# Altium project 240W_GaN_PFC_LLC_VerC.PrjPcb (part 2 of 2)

## Sheet 240W_LLC_Stage.SchDoc
size 431 x 279 mm; Date: Not shown in title block; ApprovedBy: Not shown in title block; CheckedBy: Not shown in title block; Author: Not shown in title block; CompanyName: Not shown in title block; Engineer: Not shown in title block; Organization: Not shown in title block; Address1: Not shown in title block; Address2: Not shown in title block; Address3: Not shown in title block; Address4: Not shown in title block; DocumentNumber: 3; Revision: Use project parameter SCH_Rev; SheetNumber: 3; SheetTotal: 3; PageSetup: Record=PageOptions¦CenterHorizontal=True¦CenterVertical=True¦PrintScale=1.00¦XCorrection=1.00¦YCorrection=1.00¦PrintKind=0¦BorderSize=5000000¦LeftOffset=0¦BottomOffset=0¦Orientation=2¦PaperLength=1000¦PaperWidth=1000¦Scale=100¦PaperSource=15¦PrintQuality=600¦MediaType=1¦DitherType=10¦PaperKind=Letter¦PrintScaleMode=1
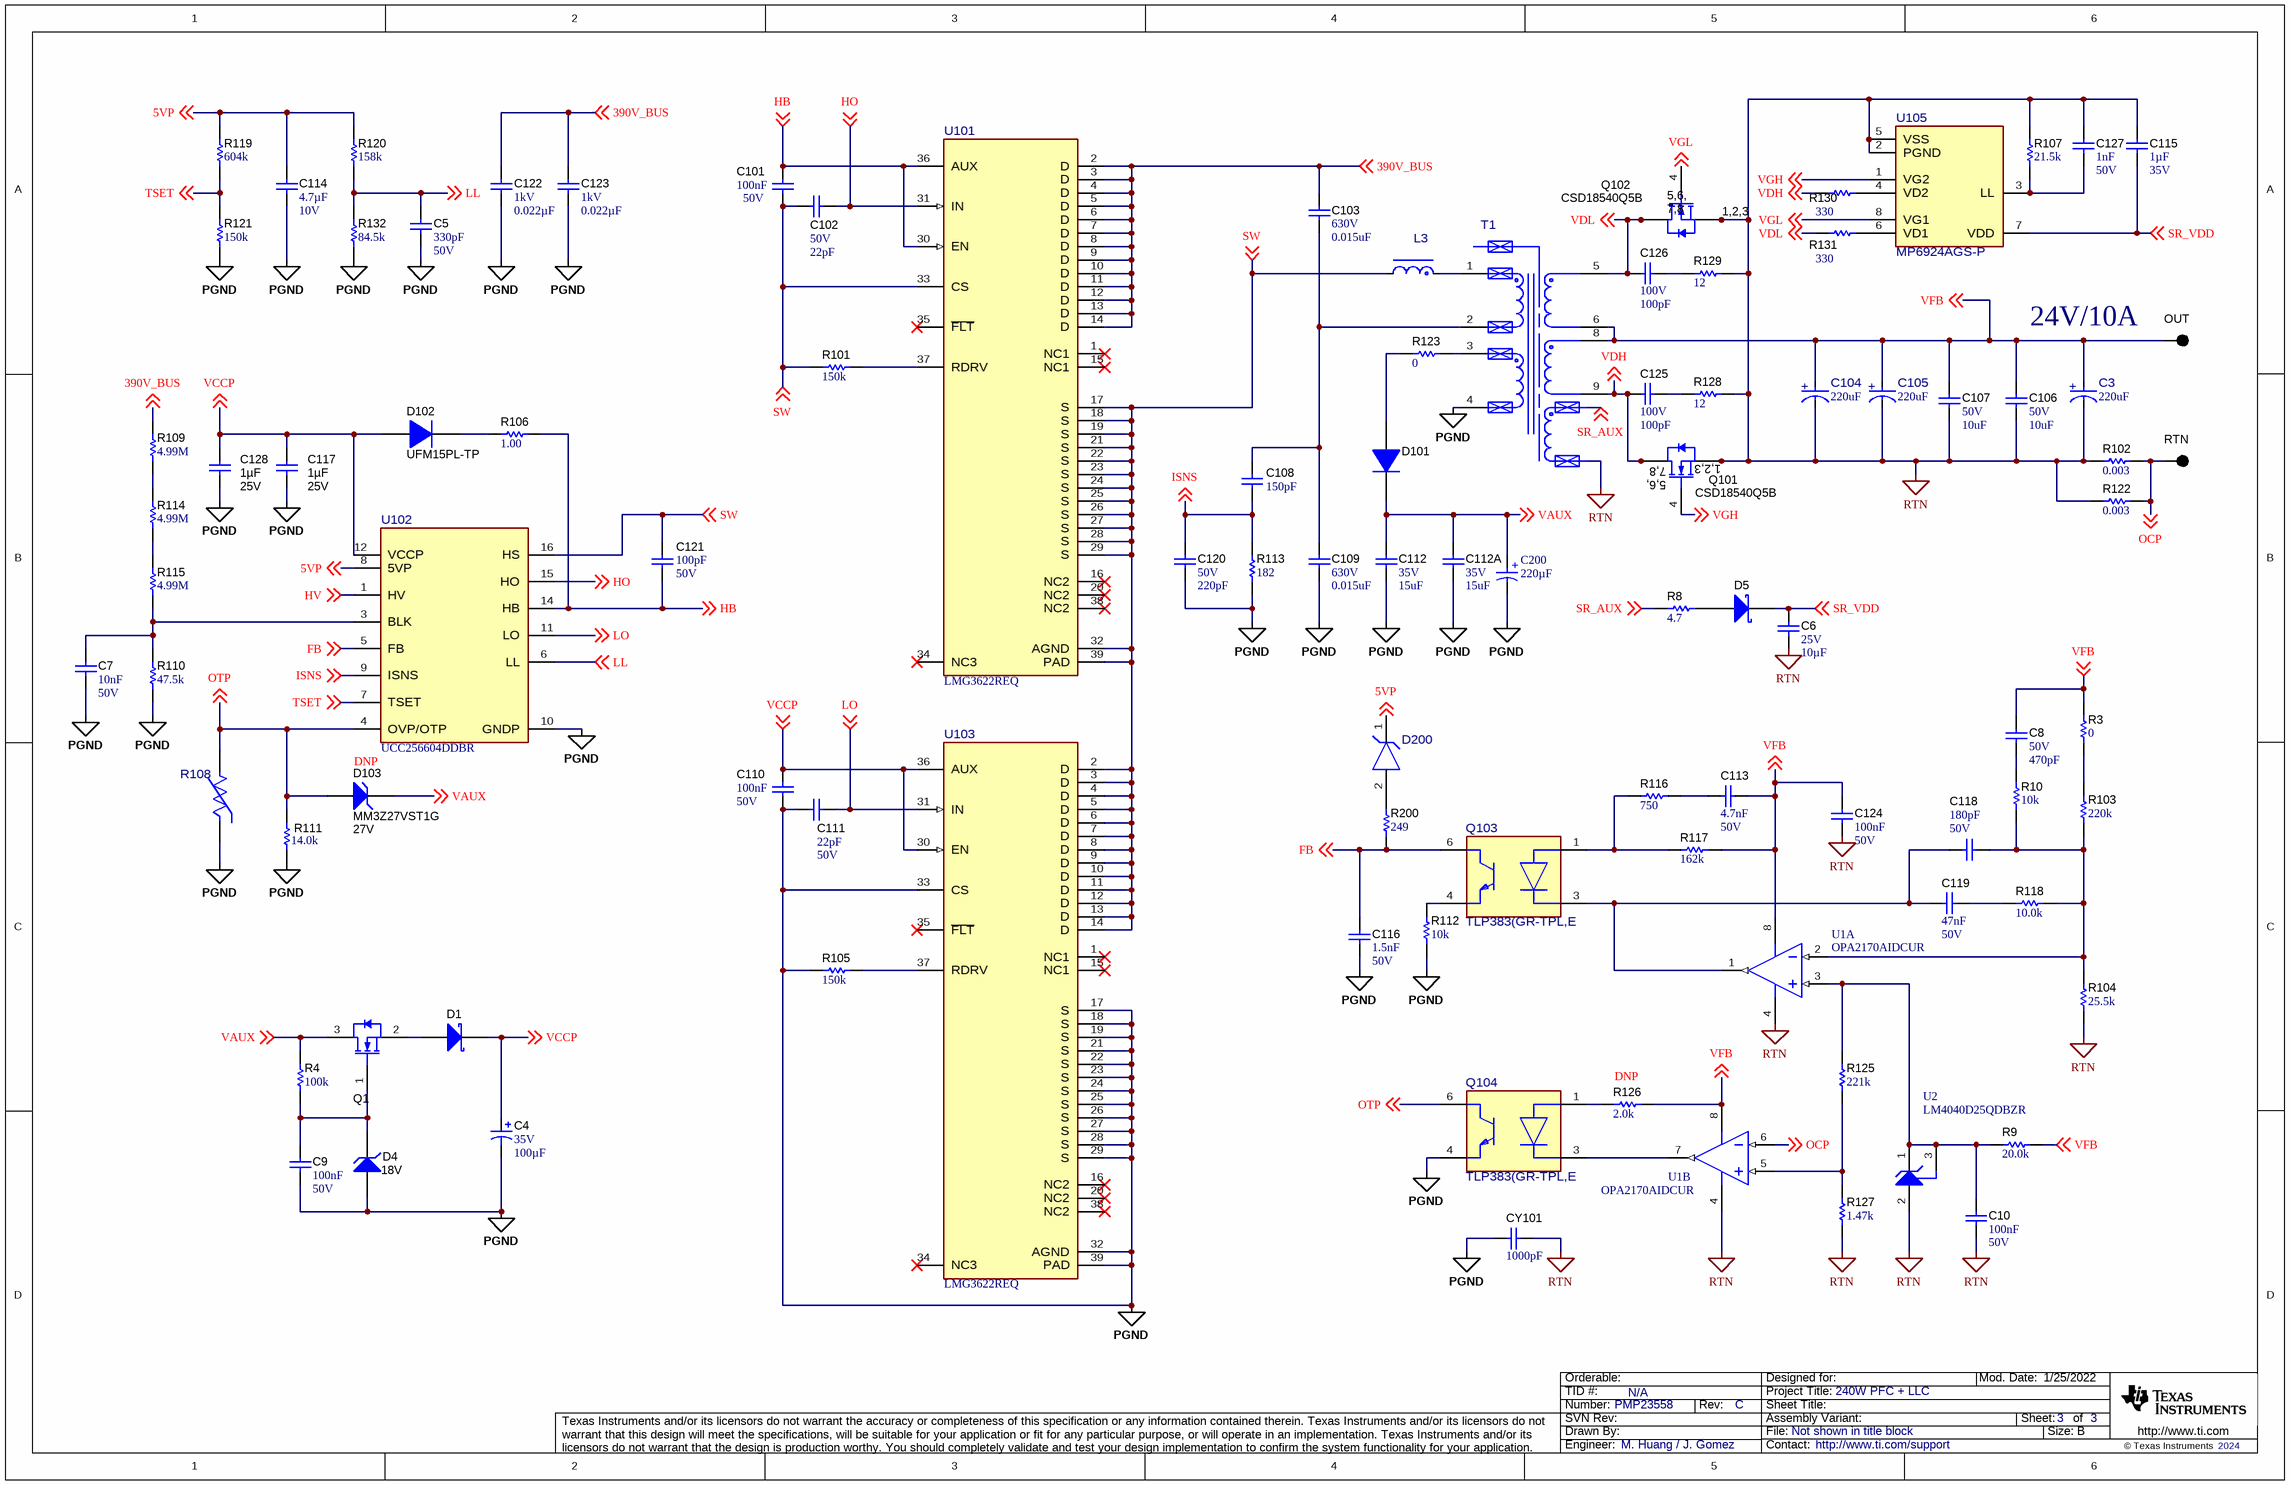
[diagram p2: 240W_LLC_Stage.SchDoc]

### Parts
C3  ValueDisplayed: 220uF  [FP-227AVG035MFBJ_RADIAL-MFG]  (hidden comment: 227AVG035MFBJ)
C4  VDC_V: 35V  ValueDisplayed: 100µF  [Rubycon_630x1100]  (hidden comment: 35ZLJ100M6.3X11)
C5  Cap_F: 330pF  VDC_V: 50V  [0603_HV]  (hidden comment: C0603C331K5RACTU)
C6  VDC_V: 25V  ValueDisplayed: 10µF  [0603_HV]  (hidden comment: GRM188R61E106KA73D)
C7  Cap_F: 10nF  VDC_V: 50V  [0603_HV]  (hidden comment: C0603C103K5RACTU)
C8  VDC_V: 50V  ValueDisplayed: 470pF  [0603_HV]  (hidden comment: 06035A471JAT2A)
C9  Cap_F: 100nF  VDC_V: 50V  [0603_HV]  (hidden comment: GCM188R71H104KA57D)
C10  Cap_F: 100nF  VDC_V: 50V  [0603_HV]  (hidden comment: 06035C104KAZ2A)
C101  Cap_F: 100nF  VDC_V: 50V  [0603_HV]  (hidden comment: 06035C104KAZ2A)
C102  VDC_V: 50V  ValueDisplayed: 22pF  [0603_HV]  (hidden comment: CGA3E2C0G1H220J080AA)
C103  VDC_V: 630V  ValueDisplayed: 0.015uF  [PHE426_1300x400x900]  (hidden comment: PHE426MA5150JR05)
C104  ValueDisplayed: 220uF  [FP-227AVG035MFBJ_RADIAL-MFG]  (hidden comment: 227AVG035MFBJ)
C105  ValueDisplayed: 220uF  [FP-227AVG035MFBJ_RADIAL-MFG]  (hidden comment: 227AVG035MFBJ)
C106  VDC_V: 50V  ValueDisplayed: 10uF  [1206_180M]  (hidden comment: CL31B106KBHNNNE)
C107  VDC_V: 50V  ValueDisplayed: 10uF  [1206_180M]  (hidden comment: CL31B106KBHNNNE)
C108  ValueDisplayed: 150pF  [1206]  (hidden comment: GRM31A5C2J151JW01D)
C109  VDC_V: 630V  ValueDisplayed: 0.015uF  [PHE426_1300x400x900]  (hidden comment: PHE426MA5150JR05)
C110  Cap_F: 100nF  VDC_V: 50V  [0603_HV]  (hidden comment: 06035C104KAZ2A)
C111  VDC_V: 50V  ValueDisplayed: 22pF  [0603_HV]  (hidden comment: CGA3E2C0G1H220J080AA)
C112  VDC_V: 35V  ValueDisplayed: 15uF  [0805_HV]  (hidden comment: C2012X5R1V156M125AC)
C112A  VDC_V: 35V  ValueDisplayed: 15uF  [0805_HV]  (hidden comment: C2012X5R1V156M125AC)
C113  Cap_F: 4.7nF  VDC_V: 50V  [0603_HV]  (hidden comment: C0603C472K5RACTU)
C114  Cap_F: 4.7µF  VDC_V: 10V  [0603_HV]  (hidden comment: GRM188Z71A475ME15D)
C115  Cap_F: 1µF  VDC_V: 35V  [0603_HV]  (hidden comment: C1608X7R1V105K080AC)
C116  Cap_F: 1.5nF  VDC_V: 50V  [0603_HV]  (hidden comment: GRM188R71H152KA01D)
C117  Cap_F: 1µF  VDC_V: 25V  [0603_HV]  (hidden comment: GRJ188R71E105KE11D)
C118  VDC_V: 50V  ValueDisplayed: 180pF  [0603_HV]  (hidden comment: 06035A181JAT2A)
C119  Cap_F: 47nF  VDC_V: 50V  [0603_HV]  (hidden comment: C1608X7R1H473K080AA)
C120  VDC_V: 50V  ValueDisplayed: 220pF  [0603_HV]  (hidden comment: GRM1885C1H221JA01D)
C121  VDC_V: 50V  ValueDisplayed: 100pF  [0603]  (hidden comment: C0603C101F5GACTU)
C122  VDC_V: 1kV  ValueDisplayed: 0.022µF  [1206_190]  (hidden comment: C1206C223KDRACTU)
C123  VDC_V: 1kV  ValueDisplayed: 0.022µF  [1206_190]  (hidden comment: C1206C223KDRACTU)
C124  Cap_F: 100nF  VDC_V: 50V  [0603_HV]  (hidden comment: C0603C104K5RACTU)
C125  VDC_V: 100V  ValueDisplayed: 100pF  [0603]  (hidden comment: C1608C0G2A101F080AA)
C126  VDC_V: 100V  ValueDisplayed: 100pF  [0603]  (hidden comment: C1608C0G2A101F080AA)
C127  Cap_F: 1nF  VDC_V: 50V  [0603_HV]  (hidden comment: C0603X102K5RACTU)
C128  Cap_F: 1µF  VDC_V: 25V  [0603_HV]  (hidden comment: GRJ188R71E105KE11D)
C200  Cap_F: 220µF  [WCAP-ATUL_D10H12.5]  (hidden comment: 860040575007)
CY101  ValueDisplayed: 1000pF  [DK1_86]  (hidden comment: DK1E3EA102M86RAH01)
D1  SD103AWS-TP  [SOD-323]  (value not drawn)
D4  value 18V  [SOD-323]  (hidden comment: MMSZ5248BS-7-F)
D5  SD103AWS-TP  [SOD-323]  (value not drawn)
D101  ES1D-E3/61T  [SMA]  (value not drawn)
D102  UFM15PL-TP  [SOD-123FL]
D103  MM3Z27VST1G  value 27V  [SOD-323]
D200  BZX84J-C3V0,115  [FP-BZX84J-B4V7,115_SC90-MFG]  (value not drawn)
L3  (no value)  [FP-G244038LF_PTH2-MFG]
Q1  2N7002-7-F  [SOT-23]  (value not drawn)
Q101  CSD18540Q5B  [DNK0008A]
Q102  CSD18540Q5B  [DNK0008A]
Q103  TLP383(GR-TPL,E  [FP-TLP383(GR-TPL,E_SO6-4-MFG]
Q104  TLP383(GR-TPL,E  [FP-TLP383(GR-TPL,E_SO6-4-MFG]
R3  ValueDisplayed: 0  [0603_HV]  (hidden comment: RC0603JR-070RL)
R4  ValueDisplayed: 100k  [0603_HV]  (hidden comment: CRCW0603100KJNEAC)
R8  ValueDisplayed: 4.7  [0603_HV]  (hidden comment: CRCW06034R70JNEA)
R9  ValueDisplayed: 20.0k  [0603_HV]  (hidden comment: CRCW060320K0FKEA)
R10  ValueDisplayed: 10k  [0603_HV]  (hidden comment: CRCW060310K0JNEA)
R101  ValueDisplayed: 150k  [0603]  (hidden comment: CRCW0603150KJNEA)
R102  ValueDisplayed: 0.003  [1206]  (hidden comment: CSNL1206FT3L00)
R103  ValueDisplayed: 220k  [0603_HV]  (hidden comment: RC0603FR-07220KL)
R104  ValueDisplayed: 25.5k  [0603_HV]  (hidden comment: RC0603FR-0725K5L)
R105  ValueDisplayed: 150k  [0603_HV]  (hidden comment: CRCW0603150KJNEA)
R106  ValueDisplayed: 1.00  [0603_HV]  (hidden comment: RC0603FR-071RL)
R107  ValueDisplayed: 21.5k  [0603_HV]  (hidden comment: RC0603FR-0721K5L)
R108  B57371V2474J060  [FP-B57371V2474J060_0603-MFG]  (value not drawn)
R109  ValueDisplayed: 4.99M  [0805_HV]  (hidden comment: CRCW08054M99FKEA)
R110  ValueDisplayed: 47.5k  [0603]  (hidden comment: RC0603FR-0747K5L)
R111  ValueDisplayed: 14.0k  [0603_HV]  (hidden comment: RC0603FR-0714KL)
R112  ValueDisplayed: 10k  [0603_HV]  (hidden comment: RC0603JR-0710KL)
R113  ValueDisplayed: 182  [0603]  (hidden comment: RC0603FR-07182RL)
R114  ValueDisplayed: 4.99M  [0805_HV]  (hidden comment: CRCW08054M99FKEA)
R115  ValueDisplayed: 4.99M  [0805_HV]  (hidden comment: CRCW08054M99FKEA)
R116  ValueDisplayed: 750  [0603_HV]  (hidden comment: CRCW0603750RFKEA)
R117  ValueDisplayed: 162k  [0603]  (hidden comment: RC0603FR-07162KL)
R118  ValueDisplayed: 10.0k  [0603_HV]  (hidden comment: M55342K12B10E0T)
R119  ValueDisplayed: 604k  [0603]  (hidden comment: CRCW0603604KFKEA)
R120  ValueDisplayed: 158k  [0603]  (hidden comment: RC0603FR-07158KL)
R121  ValueDisplayed: 150k  [0603]  (hidden comment: RC0603FR-07150KL)
R122  ValueDisplayed: 0.003  [1206]  (hidden comment: CSNL1206FT3L00)
R123  ValueDisplayed: 0  [0603]  (hidden comment: CRCW06030000Z0EA)
R125  ValueDisplayed: 221k  [0603]  (hidden comment: RC0603FR-07221KL)
R126  ValueDisplayed: 2.0k  [0603_HV]  (hidden comment: CRCW06032K00JNEA)
R127  ValueDisplayed: 1.47k  [0603_HV]  (hidden comment: RC0603FR-071K47L)
R128  ValueDisplayed: 12  [0805_HV]  (hidden comment: ERJ-6GEYJ120V)
R129  ValueDisplayed: 12  [0805_HV]  (hidden comment: ERJ-6GEYJ120V)
R130  ValueDisplayed: 330  [0603_HV]  (hidden comment: RC0603JR-07330RL)
R131  ValueDisplayed: 330  [0603_HV]  (hidden comment: RC0603JR-07330RL)
R132  ValueDisplayed: 84.5k  [0603]  (hidden comment: RC0603FR-0784K5L)
R200  ValueDisplayed: 249  [0603]  (hidden comment: CRCW0603249RFKEA)
T1  (no value)  [FP-G244036LF_PTH_XFRMR_29MM0_20MM6-MFG]
TP101  OUT  [Keystone5011]
TP106  RTN  [Keystone5011]
U1  OPA2170AIDCUR  [DCU0008A_N]  (parts A,B of 2)
U2  LM4040D25QDBZR  [DBZ0003A_N]
U101  LMG3622REQ  [REQ0038A-MFG]
U102  UCC256604DDBR  [DDB0014A-MFG]
U103  LMG3622REQ  [REQ0038A-MFG]
U105  MP6924AGS-P  [FP-MP6924AGS-P_SOIC8-MFG]

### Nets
PGND: C4.2(-) C5.2 C7.2 C9.2 C109.2 C110.2 C111.2 C112.2 C112A.2 C114.2 C116.2 C117.1 C120.2 C122.2 C123.2 C128.1 C200.2(N) CY101.2 D4.2(A) Q104.4(Emitter) R105.1 R108.1 R110.1 R111.1 R112.1 R113.1 R121.1 R132.1 T1.4 U102.10(GNDP) U103.17(S) U103.18(S) U103.19(S) U103.21(S) U103.22(S) U103.23(S) U103.24(S) U103.25(S) U103.26(S) U103.27(S) U103.28(S) U103.29(S) U103.32(AGND) U103.33(CS) U103.39(PAD)
RTN: C3.1(CATHODE) C6.2 C10.2 C104.1(CATHODE) C105.1(CATHODE) C106.2 C107.2 C115.2 C124.2 C127.1 CY101.1 Q101.1(S) Q101.2(S) Q101.3(S) Q102.1(S) Q102.2(S) Q102.3(S) R102.1 R104.1 R107.1 R122.1 R127.1 R128.2 R129.2 U1.4(V-) U2.2(ANODE) U105.2(PGND) U105.5(VSS)
5VP: C114.1 D200.1(cathode) R119.2 R120.2 U102.8(5VP) ; off-sheet 5VP
390V_BUS: C103.1 C122.1 C123.1 R109.2 U101.2(D) U101.3(D) U101.4(D) U101.5(D) U101.6(D) U101.7(D) U101.8(D) U101.9(D) U101.10(D) U101.11(D) U101.12(D) U101.13(D) U101.14(D) ; off-sheet 390V_BUS
FB: C116.1 Q103.6(Collector) R200.1 U102.5(FB) ; off-sheet FB
HB: C101.1 C121.2 R106.2 U101.30(EN) U101.36(AUX) U102.14(HB) ; off-sheet HB
HO: C102.1 U101.31(IN) U102.15(HO) ; off-sheet HO
HV: U102.1(HV) ; off-sheet HV
ISNS: C108.2 C120.1 R113.2 U102.9(ISNS) ; off-sheet ISNS
LL: C5.1 R120.1 R132.2 U102.6(LL) ; off-sheet LL
LO: C111.1 U102.11(LO) U103.31(IN) ; off-sheet LO
OCP: R102.2 R122.2 TP106.1 U1.6(IN_B-) ; off-sheet OCP
OTP: D103.2(A) Q104.6(Collector) R108.2 R111.2 U102.4(OVP/OTP) ; off-sheet OTP
SR_AUX: R8.1 ; off-sheet SR_AUX
SR_VDD: C6.1 C115.1 D5.1(K) U105.7(VDD) ; off-sheet SR_VDD
SW: C101.2 C102.2 C121.1 L3.4 R101.1 U101.17(S) U101.18(S) U101.19(S) U101.21(S) U101.22(S) U101.23(S) U101.24(S) U101.25(S) U101.26(S) U101.27(S) U101.28(S) U101.29(S) U101.32(AGND) U101.33(CS) U101.39(PAD) U102.16(HS) U103.2(D) U103.3(D) U103.4(D) U103.5(D) U103.6(D) U103.7(D) U103.8(D) U103.9(D) U103.10(D) U103.11(D) U103.12(D) U103.13(D) U103.14(D) ; off-sheet SW
TSET: R119.1 R121.2 U102.7(TSET) ; off-sheet TSET
VAUX: C112.1 C112A.1 C200.1(P) D101.1(K) D103.1(K) Q1.3(D) R4.2 ; off-sheet VAUX
VCCP: C4.1(+) C110.1 C117.2 C128.2 D1.1(K) D102.2(A) U102.12(VCCP) U103.30(EN) U103.36(AUX) ; off-sheet VCCP
VDH: C125.2 Q101.5(D) Q101.6(D) Q101.7(D) Q101.8(D) Q101.9(D) R130.1 T1.9 ; off-sheet VDH
VDL: C126.2 Q102.5(D) Q102.6(D) Q102.7(D) Q102.8(D) Q102.9(D) R131.1 T1.5 ; off-sheet VDL
VFB: C3.2(ANODE) C8.1 C104.2(ANODE) C105.2(ANODE) C106.1 C107.1 C113.1 C124.1 R3.2 R9.2 R117.2 R126.1 T1.6 T1.8 TP101.1 U1.8(V+) ; off-sheet VFB
VGH: Q101.4(G) U105.1(VG2) ; off-sheet VGH
VGL: Q102.4(G) U105.8(VG1) ; off-sheet VGL
NetC7_1: C7.1 R110.2 R115.1 U102.3(BLK)
NetC8_2: C8.2 R10.2
NetC9_1: C9.1 D4.1(K) Q1.1(G) R4.1
NetC10_1: C10.1 R9.1 R125.2 U1.3(IN_A+) U2.1(CATHODE) U2.3(NC)
NetC103_2: C103.2 C108.1 C109.1 T1.2
NetC113_2: C113.2 R116.2
NetC118_1: C118.1 R10.1 R103.1 R104.2 R118.2 U1.2(IN_A-)
NetC118_2: C118.2 C119.2 Q103.3(Cathode) U1.1(OUT_A)
NetC119_1: C119.1 R118.1
NetC125_1: C125.1 R128.1
NetC126_1: C126.1 R129.1
NetC127_2: C127.2 R107.2 U105.3(LL)
NetD1_2: D1.2(A) Q1.2(S)
NetD5_2: D5.2(A) R8.2
NetD101_2: D101.2(A) R123.1
NetD102_1: D102.1(K) R106.1
NetD200_2: D200.2(anode) R200.2
NetL3_1: L3.1 T1.1
NetQ103_1: Q103.1(Anode) R116.1 R117.1
NetQ103_4: Q103.4(Emitter) R112.2
NetQ104_1: Q104.1(Anode) R126.2
NetQ104_3: Q104.3(Cathode) U1.7(OUT_B)
NetR3_1: R3.1 R103.2
NetR101_2: R101.2 U101.37(RDRV)
NetR105_2: R105.2 U103.37(RDRV)
NetR109_1: R109.1 R114.2
NetR114_1: R114.1 R115.2
NetR123_2: R123.2 T1.3
NetR125_1: R125.1 R127.2 U1.5(IN_B+)
NetR130_2: R130.2 U105.4(VD2)
NetR131_2: R131.2 U105.6(VD1)

Not connected (* = marked no-connect by the designer): U101 1(NC1)* 15(NC1)* 16(NC2)* 20(NC2)* 34(NC3)* 35(~{FLT})* 38(NC2)*; U103 1(NC1)* 15(NC1)* 16(NC2)* 20(NC2)* 34(NC3)* 35(~{FLT})* 38(NC2)*

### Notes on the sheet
- 24V/10A
- DNP
- (near R126) DNP

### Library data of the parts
C3 C104 C105 = CMP-0121632-1: 220 µF 35 V Aluminum - Polymer Capacitors Radial, Can 26mOhm 1500 Hrs @ 125°C; Manufacturer: Cornell Dubilier; AEC Qualified: No; Cap_F: 220µF; IRMS_A: 2.95A; SizeZ_mm: 13.5mm; Tolerance_%: 20%; VDC_V: 35V; Dissipation Factor: 12%; Esr: 26m; Leakage Current: 1540uA; Life: 1500Hours; Value: 220µF
C4 = CMP-0080807-1: CAP, AL, 100 µF, 35 V, +/- 20%, TH; Manufacturer: Rubycon; IRMS_A: 700mA; SizeAreaWB_mm2: 68.89; SizeArea_mm2: 39.69; AEC Qualified: N; AEC Category: Q200; Value: 100uF; TaMax_C: 105°C; SizeZ_mm: 12.5; Polarized: Y; TaMin_C: -40°C; SizeY_mm: 6.3; U/M: EA; CompType: Capacitor; Cap_Case: 6.3x11
C5 = CMP-0006921-2: CAP, CERM, 330 pF, 50 V, +/- 10%, X7R, 0603; Manufacturer: Kemet; TaMin_C: -55°C; Polarized: N; SizeAreaWB_mm2: 4.68; Value1: Unknown; U/M: EA; Value: 330pF; TaMax_C: 125°C; SizeZ_mm: 1; SizeX_mm: 1.6; SizeY_mm: 0.8; Cap_Case: 0603; SizeArea_mm2: 1.28; AEC Category: Q200
C6 = CMP-0860569-1: CAP, CERM, 10 µF, 25 V,+/- 10%, X5R, 0603; Manufacturer: MuRata; SizeZ_mm: 1; AEC Category: Q200; AEC Qualified: N; TaMin_C: -55°C; Cap_Case: 0603; SizeY_mm: 0.8; SizeAreaWB_mm2: 4.68; SizeArea_mm2: 1.28; TaMax_C: 85°C; SizeX_mm: 1.6; Value: 10uF; U/M: EA
C7 = CMP-0006854-1: CAP, CERM, 0.01 uF, 50 V, +/- 10%, X7R, 0603; Manufacturer: Kemet; TaMin_C: -55°C; Polarized: N; SizeAreaWB_mm2: 4.68; Value1: Unknown; U/M: EA; Value: 0.01uF; TaMax_C: 125°C; SizeZ_mm: 1; SizeX_mm: 1.6; SizeY_mm: 0.8; Cap_Case: 0603; SizeArea_mm2: 1.28; AEC Category: Q200
C8 = CMP-0006790-2: CAP, CERM, 470 pF, 50 V, +/- 5%, C0G/NP0, 0603; Manufacturer: AVX; TaMin_C: -55°C; ESR_ohm: 63m; Polarized: N; SizeAreaWB_mm2: 4.68; Value1: 0.063 ohm; U/M: EA; Value: 470pF; TaMax_C: 125°C; SizeZ_mm: 1; SizeX_mm: 1.6; SizeY_mm: 0.8; Cap_Case: 0603; SizeArea_mm2: 1.28; AEC Category: Q200
C9 = CMP-0007144-2: CAP, CERM, 0.1 uF, 50 V, +/- 10%, X7R, 0603; Manufacturer: MuRata; TaMin_C: -55°C; ESR_ohm: 20m; Polarized: N; SizeAreaWB_mm2: 4.68; Value1: 0.02 ohm; U/M: EA; Value: 0.1uF; TaMax_C: 125°C; SizeZ_mm: 1; SizeX_mm: 1.6; SizeY_mm: 0.8; Cap_Case: 0603; SizeArea_mm2: 1.28; IRMS_A: 1.84A; AEC Category: Q200
C10 C101 C110 = CMP-0079095-1: CAP, CERM, 0.1 µF, 50 V,+/- 10%, X7R, AEC-Q200 Grade 1, 0603; Manufacturer: AVX; SizeAreaWB_mm2: 4.68; SizeArea_mm2: 1.28; AEC Qualified: Y; AEC Category: Q200; Value: 0.1uF; TaMax_C: 125°C; SizeZ_mm: 1; Polarized: N; TaMin_C: -55°C; SizeY_mm: 0.8; U/M: EA; SizeX_mm: 1.6; Cap_Case: 0603; ValueDisplayed: 0.1µF
C102 C111 = CMP-0007071-4: CAP, CERM, 22 pF, 50 V, +/- 5%, C0G/NP0, AEC-Q200 Grade 1, 0603; Manufacturer: TDK; TaMin_C: -55°C; Polarized: N; SizeAreaWB_mm2: 4.68; Value1: Unknown; U/M: EA; Value: 22pF; TaMax_C: 125°C; SizeZ_mm: 1; SizeX_mm: 1.6; SizeY_mm: 0.8; Cap_Case: 0603; SizeArea_mm2: 1.28; AEC Qualified: Y; AEC Category: Q200
C103 C109 = CMP-0012541-3: CAP, Film, 0.015 uF, 630 V, +/- 20%, TH; Manufacturer: Kemet; TaMin_C: -55°C; Polarized: N; SizeAreaWB_mm2: 90; Value1: Unknown; TaMax_C: 105°C; SizeZ_mm: 9; SizeX_mm: 13; SizeY_mm: 4; Cap_Case: 13x4x9mm; SizeArea_mm2: 52; Cap_F: 15nF; AEC Category: Q200
C106 C107 = CMP-0008802-1: CAP, CERM, 10 uF, 50 V, +/- 10%, X7R, 1206; Manufacturer: Samsung; TaMin_C: -55°C; Polarized: N; SizeAreaWB_mm2: 10.92; Value1: Unknown; U/M: EA; Value: 10uF; TaMax_C: 125°C; SizeZ_mm: 1.8; SizeX_mm: 3.2; SizeY_mm: 1.6; Cap_Case: 1206; SizeArea_mm2: 5.12; Cap_F: 10µF; AEC Category: Q200
C108 = CMP-0008885-2: CAP, CERM, 150 pF, 630 V, +/- 5%, C0G/NP0, 1206; Manufacturer: MuRata; TaMin_C: -55°C; Polarized: N; SizeAreaWB_mm2: 10.92; Value1: Unknown; U/M: EA; Value: 150pF; TaMax_C: 125°C; SizeZ_mm: 1.35; SizeX_mm: 3.2; SizeY_mm: 1.6; Value2: 630V; SizeArea_mm2: 5.12; AEC Category: Q200
C112 C112A = CMP-0007843-1: CAP, CERM, 15 uF, 35 V, +/- 20%, X5R, 0805; Manufacturer: TDK; TaMin_C: -55°C; ESR_ohm: 1.669m; Polarized: N; SizeAreaWB_mm2: 6.75; Value1: 0.001669 ohm; U/M: EA; Value: 15uF; TaMax_C: 85°C; SizeZ_mm: 1.45; SizeX_mm: 2; SizeY_mm: 1.25; Cap_Case: 0805; SizeArea_mm2: 2.5; Cap_F: 15µF; IRMS_A: 5.0498A; AEC Category: Q200
C113 = CMP-0006943-4: CAP, CERM, 4700 pF, 50 V, +/- 10%, X7R, 0603; Manufacturer: Kemet; TaMin_C: -55°C; Polarized: N; SizeAreaWB_mm2: 4.68; Value1: Unknown; U/M: EA; Value: 4700pF; TaMax_C: 125°C; SizeZ_mm: 1; SizeX_mm: 1.6; SizeY_mm: 0.8; Cap_Case: 0603; SizeArea_mm2: 1.28; AEC Category: Q200
C114 = CMP-0007498-4: CAP, CERM, 4.7 uF, 10 V, +/- 20%, X7R, 0603; Manufacturer: MuRata; TaMin_C: -55°C; Polarized: N; SizeAreaWB_mm2: 4.68; Value1: Unknown; U/M: EA; Value: 4.7uF; TaMax_C: 125°C; SizeZ_mm: 1; SizeX_mm: 1.6; SizeY_mm: 0.8; Cap_Case: 0603; SizeArea_mm2: 1.28; AEC Category: Q200
C115 = CMP-0007052-4: CAP, CERM, 1 uF, 35 V, +/- 10%, X7R, 0603; Manufacturer: TDK; TaMin_C: -55°C; Polarized: N; SizeAreaWB_mm2: 4.68; Value1: Unknown; U/M: EA; Value: 1uF; TaMax_C: 125°C; SizeZ_mm: 1; SizeX_mm: 1.6; SizeY_mm: 0.8; Cap_Case: 0603; SizeArea_mm2: 1.28; AEC Category: Q200
C116 = CMP-0007437-3: CAP, CERM, 1500 pF, 50 V, +/- 10%, X7R, 0603; Manufacturer: MuRata; TaMin_C: -55°C; Polarized: N; SizeAreaWB_mm2: 4.68; Value1: Unknown; U/M: EA; Value: 1500pF; TaMax_C: 125°C; SizeZ_mm: 1; SizeX_mm: 1.6; SizeY_mm: 0.8; Cap_Case: 0603; SizeArea_mm2: 1.28; AEC Category: Q200
C117 C128 = CMP-0079720-1: CAP, CERM, 1 µF, 25 V,+/- 10%, X7R, 0603; Manufacturer: MuRata; TaMin_C: -55°C; Polarized: N; SizeAreaWB_mm2: 4.68; U/M: EA; Value: 1uF; TaMax_C: 125°C; SizeZ_mm: 1; SizeX_mm: 1.6; SizeY_mm: 0.8; Cap_Case: 0603; SizeArea_mm2: 1.28; AEC Category: Q200
C118 = CMP-0006770-4: CAP, CERM, 180 pF, 50 V, +/- 5%, C0G/NP0, 0603; Manufacturer: AVX; TaMin_C: -55°C; ESR_ohm: 90m; Polarized: N; SizeAreaWB_mm2: 4.68; Value1: 0.09 ohm; U/M: EA; Value: 180pF; TaMax_C: 125°C; SizeZ_mm: 1; SizeX_mm: 1.6; SizeY_mm: 0.8; Cap_Case: 0603; SizeArea_mm2: 1.28; AEC Category: Q200
C119 = CMP-0007049-4: CAP, CERM, 0.047 uF, 50 V, +/- 10%, X7R, 0603; Manufacturer: TDK; TaMin_C: -55°C; ESR_ohm: 49.007m; Polarized: N; SizeAreaWB_mm2: 4.68; Value1: 0.049007 ohm; U/M: EA; TaMax_C: 125°C; SizeZ_mm: 1; SizeX_mm: 1.6; SizeY_mm: 0.8; Cap_Case: 0603; SizeArea_mm2: 1.28; IRMS_A: 767.528mA; AEC Category: Q200
C120 = CMP-0007197-1: CAP, CERM, 220 pF, 50 V, +/- 5%, C0G/NP0, 0603; Manufacturer: MuRata; TaMin_C: -55°C; Polarized: N; SizeAreaWB_mm2: 4.68; Value1: Unknown; U/M: EA; Value: 220pF; TaMax_C: 125°C; SizeZ_mm: 1; SizeX_mm: 1.6; SizeY_mm: 0.8; Cap_Case: 0603; SizeArea_mm2: 1.28; AEC Category: Q200
C121 = CMP-0080091-1: CAP, CERM, 100 pF, 50 V,+/- 1%, C0G/NP0, 0603; Manufacturer: Kemet; SizeAreaWB_mm2: 4.68; SizeArea_mm2: 1.28; AEC Qualified: N; AEC Category: Q200; Value: 100pF; TaMax_C: 125°C; SizeZ_mm: 1; Green_REACh: Passed; TaMin_C: -55°C; SizeY_mm: 0.8; Green_Lifecycle: Active; U/M: EA; SizeX_mm: 1.6
C122 C123 = CMP-0084048-1: CAP, CERM, 0.022 µF, 1000 V,+/- 10%, X7R, AEC-Q200 Grade 1, 1206; Manufacturer: Kemet; TaMin_C: -55°C; Polarized: N; SizeAreaWB_mm2: 10.92; U/M: EA; Value: 0.022uF; TaMax_C: 125°C; SizeZ_mm: 1.9; SizeX_mm: 3.2; SizeY_mm: 1.6; Cap_Case: 1206; Value2: 1000V; SizeArea_mm2: 5.12; AEC Qualified: Y; Cap_F: 22nF; AEC Grade: 1; AEC Category: Q200
C124 = CMP-0006861-4: CAP, CERM, 0.1 uF, 50 V, +/- 10%, X7R, 0603; Manufacturer: Kemet; TaMin_C: -55°C; Polarized: N; SizeAreaWB_mm2: 4.68; Value1: Unknown; U/M: EA; Value: 0.1uF; TaMax_C: 125°C; SizeZ_mm: 1; SizeX_mm: 1.6; SizeY_mm: 0.8; Cap_Case: 0603; SizeArea_mm2: 1.28; AEC Category: Q200
C125 C126 = CMP-0006992-4: CAP, CERM, 100 pF, 100 V, +/- 1%, C0G/NP0, 0603; Manufacturer: TDK; TaMin_C: -55°C; Polarized: N; SizeAreaWB_mm2: 4.68; Value1: Unknown; U/M: EA; Value: 100pF; TaMax_C: 125°C; SizeZ_mm: 1; SizeX_mm: 1.6; SizeY_mm: 0.8; SizeArea_mm2: 1.28; AEC Category: Q200
C127 = CMP-0006976-5: CAP, CERM, 1000 pF, 50 V, +/- 10%, X7R, 0603; Manufacturer: Kemet; TaMin_C: -55°C; Polarized: N; SizeAreaWB_mm2: 4.68; Value1: Unknown; U/M: EA; Value: 1000pF; TaMax_C: 125°C; SizeZ_mm: 1; SizeX_mm: 1.6; SizeY_mm: 0.8; Cap_Case: 0603; SizeArea_mm2: 1.28; AEC Category: Q200
C200 = CMP-0113274-1: WCAP-ATUL Aluminum Electrolytic Capacitor, Radial, THT, D10 x H12.5mm, 220µF, 35V; Manufacturer: Wurth Elektronik; Capacitance Tolerance: 20%; Dissipation Factor: 12%; Endurance: 7000h; Leakage Current: 77uA; Ripple Current: 1060mA; Technical Reference: ATDF125221M035DSPA9G000
CY101 = CMP-0077997-1: CAP, CERM, 1000 pF, X1 440 VAC/Y1 250 VAC, +/- 20%, E, 8x6mm; Manufacturer: MuRata; Cap_F: 1nF; VAC_X: 440; SizeAreaWB_mm2: 107.2; VAC_Y: 250; SizeArea_mm2: 68.4; AEC Qualified: N; AEC Category: Q200; Value: 1000pF; TaMax_C: 125°C; SizeZ_mm: 2.5; TaMin_C: -40°C; SizeY_mm: 6; U/M: EA; AC_Safety: X1Y1; SizeX_mm: 11.4
D1 D5 = CMP-0076928-2: Diode, Schottky, 40 V, 0.35 A, SOD-323; Manufacturer: Micro Commercial Components; Value: 40V; SizeX_mm: 2.7; SizeAreaWB_mm2: 8.695; AEC Category: Q101; Vf_V: 600mV; SizeArea_mm2: 3.645; Green_Lifecycle: Not Set; SizeY_mm: 1.35; Io_A: 350mA; SizeZ_mm: 1.0; Green_REACh: Incomplete; Value2: 0.6V; Value1: 0.35A
D4 = CMP-0005835-4: Diode, Zener, 18 V, 200 mW, SOD-323; Manufacturer: Diodes Inc.; Value1: 0.2W; SizeArea_mm2: 3.645; AEC Category: Q101; Power_W: 200mW; SizeAreaWB_mm2: 8.695; SizeY_mm: 1.35; RJA_CperW: 350; SizeZ_mm: 1; SizeX_mm: 2.7
D101 = CMP-0082147-2: Diode, Ultrafast, 200 V, 1 A, AEC-Q101, SMA; Manufacturer: Vishay-Semiconductor; SizeAreaWB_mm2: 37.3428; AEC Qualified: Y; SizeY_mm: 2.92; AEC Category: Q101; SizeArea_mm2: 16.3228; Io_A: 1A; Value2: 0.92V; SizeZ_mm: 2.87; SizeX_mm: 5.59; TJmax_C: 150°C; Vf_V: 920mV; Vr_V: 200V; Value: 200V
D102 = CMP-0029148-2: Diode, Ultrafast, 600 V, 1 A, SOD-123FL; Manufacturer: Micro Commercial Components; SizeY_mm: 1.65; Value: 600V; Io_A: 1A; Green_Lifecycle: Not Set; Green_REACh: Incomplete; SizeX_mm: 3.6; SizeAreaWB_mm2: 12.19; SizeArea_mm2: 5.94; AEC Qualified: N; Value2: 1.7V; SizeZ_mm: 0.98; AEC Category: Q101; TJmax_C: 150°C
D103 = CMP-0085773-1: Diode, Zener, 27 V, 300 mW, SOD-323; Manufacturer: ON Semiconductor; RJA_CperW: 416; Power_W: 300mW; AEC Qualified: N; AEC Category: Q101; SizeArea_mm2: 3.645; SizeX_mm: 2.7; SizeZ_mm: 1; SizeY_mm: 1.35; SizeAreaWB_mm2: 8.695; Value1: 0.3W
D200 = CMP-0097377-1: Diode Zener Single 4.7V 2% 550mW Automotive 2-Pin SOD-323F T/R; Manufacturer: Nexperia; Vf_V: 4.79V; TaMin_C: -55°C; SizeZ_mm: 0.8mm; Max Reverse Leakage Current: 3uA; TJmax_C: 150°C; Zener Impedance: 80Ω; AEC Grade: Grade 0; Forward Current: 250mA; TaMax_C: +150°C; AEC Qualified: Yes
L3 = CMP-0123590-1: RESONANT INDUCTOR; Manufacturer: 3L; PartNumber: ATQ18-43UH-MY; AEC Qualified: No; DCR_ohm: 17m; Ind_H: 43µH; SizeZ_mm: 17.7mm; Value: 43uH; Test Frequency: 100kHz; Tolerance_%: 5%
Q1 = CMP-0000769-1: MOSFET, N-CH, 60 V, 0.17 A, SOT-23; Alternate Manufacturer: None; Manufacturer: Diodes Inc.; SizeZ_mm: 1.1; ChType: N; Value2: 223 nC; Value1: 7; VdsMax_V: 60V; SizeX_mm: 2.5; SizeY_mm: 3; Vgs_V: 20V; Value: 60V; Rdson45_ohm: 7.5; AEC Category: Q101; IdsMax_A: 1.7dA; SizeAreaWB_mm2: 14; U/M: EA; QgTyp_nC: 223
Q101 Q102 = CMP-0000823-1: MOSFET, N-CH, 60 V, 100 A, DNK0008A (VSON-CLIP-8); Alternate Manufacturer: None; Manufacturer: Texas Instruments; SizeZ_mm: 1; ChType: N; Value2: 41 nC; Value1: 0.003; VdsMax_V: 60V; SizeX_mm: 6; SizeY_mm: 5; Vgs_V: 20V; Value: 60V; Rdson45_ohm: 3.3m; SizeArea_mm2: 30; AEC Category: Q101; IdsMax_A: 100A; SizeAreaWB_mm2: 56; U/M: EA; QgTyp_nC: 41
Q103 Q104 = CMP-0087394-2: Optoisolator Transistor Output 5000Vrms 1 Channel 6-SO; Manufacturer: Toshiba; CTR (Max): 300%; CTR (Min): 100%; SizeZ_mm: 2.3mm
R3 = CMP-0025885-5: RES, 0, 5%, 0.1 W, 0603; Manufacturer: Yageo; Power_W: 100mW; TempCo: 200 ppm/C; Value_Code: 0000; Value: 0; EIA_Code: E24; SizeX_mm: 1.6; SizeZ_mm: 1; Value2: 0.1W; SizeArea_mm2: 1.28; AEC Qualified: N; VDC_V: 75V; AEC Category: Q200; SizeY_mm: 0.8; SizeAreaWB_mm2: 4.68
R4 = CMP-0082530-1: RES, 100 k, 5%, 0.1 W, 0603; Manufacturer: Vishay-Dale; Power_W: 100mW; TempCo: 200 ppm/C; SizeAreaWB_mm2: 4.68; Value: 100k; EIA_Code: E24; SizeX_mm: 1.6; SizeY_mm: 0.8; SizeZ_mm: 1; Value2: 0.1W; SizeArea_mm2: 1.28; AEC Qualified: N; VDC_V: 75V; AEC Category: Q200
R8 = CMP-0025821-4: RES, 4.7, 5%, 0.1 W, AEC-Q200 Grade 0, 0603; Manufacturer: Vishay-Dale; Power_W: 100mW; TempCo: 200 ppm/C; Value_Code: 4R70; Value: 4.7; EIA_Code: E24; SizeX_mm: 1.6; SizeY_mm: 0.8; SizeZ_mm: 1; Value2: 0.1W; SizeArea_mm2: 1.28; AEC Qualified: Y; VDC_V: 75V; AEC Category: Q200; AEC Grade: 0
R9 = CMP-0022204-4: RES, 20.0 k, 1%, 0.1 W, AEC-Q200 Grade 0, 0603; Manufacturer: Vishay-Dale; Power_W: 100mW; TempCo: 100 ppm/C; Value_Code: 20k0; Value: 20.0k; EIA_Code: E96; Res_ohm: 20k; SizeX_mm: 1.6; SizeY_mm: 0.8; SizeZ_mm: 1; Value2: 0.1W; SizeArea_mm2: 1.28; AEC Qualified: Y; VDC_V: 75V; AEC Category: Q200; AEC Grade: 0
R10 = CMP-0025701-1: RES, 10 k, 5%, 0.1 W, 0603; Manufacturer: Vishay-Dale; Power_W: 100mW; TempCo: 200 ppm/C; Value_Code: 10k0; U/M: EA; Value: 10k; EIA_Code: E24; SizeX_mm: 1.6; SizeY_mm: 0.8; SizeZ_mm: 1; Value2: 0.1W; SizeArea_mm2: 1.28; VDC_V: 75V; AEC Category: Q200
R101 R105 = CMP-0025717-4: RES, 150 k, 5%, 0.1 W, AEC-Q200 Grade 0, 0603; Manufacturer: Vishay-Dale; Power_W: 100mW; TempCo: 200 ppm/C; Value: 150k; EIA_Code: E24; SizeX_mm: 1.6; SizeY_mm: 0.8; SizeZ_mm: 1; Value2: 0.1W; SizeArea_mm2: 1.28; AEC Qualified: Y; VDC_V: 75V; AEC Category: Q200; AEC Grade: 0
R102 R122 = CMP-0017255-2: RES, 0.003, 1%, 1 W, 1206; Manufacturer: Stackpole Electronics Inc; Power_W: 1W; TempCo: 50 ppm/C; Value_Code: 3L000; U/M: EA; Value: 0.003; EIA_Code: E96; Res_ohm: 3m; SizeX_mm: 3.2; SizeY_mm: 1.6; SizeZ_mm: 1.35; SizeArea_mm2: 5.12; AEC Category: Q200
R103 = CMP-0022917-4: RES, 220 k, 1%, 0.1 W, 0603; Manufacturer: Yageo; Power_W: 100mW; TempCo: 100 ppm/C; Value: 220k; SizeX_mm: 1.6; SizeY_mm: 0.8; SizeZ_mm: 1; Value2: 0.1W; SizeArea_mm2: 1.28; AEC Qualified: N; VDC_V: 75V; AEC Category: Q200; SizeAreaWB_mm2: 4.68
R104 = CMP-0022951-5: RES, 25.5 k, 1%, 0.1 W, 0603; Manufacturer: Yageo; Power_W: 100mW; TempCo: 100 ppm/C; Value_Code: 25k5; Value: 25.5k; EIA_Code: E96; SizeX_mm: 1.6; SizeY_mm: 0.8; SizeZ_mm: 1; Value2: 0.1W; SizeArea_mm2: 1.28; AEC Qualified: N; VDC_V: 75V; AEC Category: Q200; SizeAreaWB_mm2: 4.68
R106 = CMP-0022900-4: RES, 1.00, 1%, 0.1 W, 0603; Manufacturer: Yageo; Power_W: 100mW; TempCo: 200 ppm/C; Value_Code: 1R00; Value: 1.00; EIA_Code: E96; Res_ohm: 1; SizeX_mm: 1.6; SizeY_mm: 0.8; Value2: 0.1W; SizeArea_mm2: 1.28; AEC Qualified: N; VDC_V: 75V; AEC Category: Q200; SizeAreaWB_mm2: 4.68
R107 = CMP-0022913-5: RES, 21.5 k, 1%, 0.1 W, 0603; Manufacturer: Yageo; Power_W: 100mW; TempCo: 100 ppm/C; Value_Code: 21k5; Value: 21.5k; EIA_Code: E96; SizeX_mm: 1.6; SizeY_mm: 0.8; SizeZ_mm: 1; Value2: 0.1W; SizeArea_mm2: 1.28; AEC Qualified: N; VDC_V: 75V; AEC Category: Q200; SizeAreaWB_mm2: 4.68
R108 = CMP-0096703-1: NTC Thermistor 470k 0603 (1608 Metric); Manufacturer: TDK; AEC Qualified: No; Res_ohm: 470kΩ; Power_W: 180mW; B 25 50: 4386K; B 25 100: 4480K; SizeZ_mm: 0.9mm; B 25 85: 4455K; B Tolerance: 3%; Tolerance_%: 5%
R109 R114 R115 = CMP-0021304-3: RES, 4.99 M, 1%, 0.125 W, AEC-Q200 Grade 0, 0805; Manufacturer: Vishay-Dale; Power_W: 125mW; TempCo: 100 ppm/C; Value_Code: 4M99; Value: 4.99Meg; EIA_Code: E96; SizeX_mm: 2; SizeY_mm: 1.25; SizeZ_mm: 1.45; Value2: 0.125W; SizeArea_mm2: 2.5; AEC Qualified: Y; VDC_V: 150V; AEC Category: Q200; AEC Grade: 0
R110 = CMP-0023132-5: RES, 47.5 k, 1%, 0.1 W, 0603; Manufacturer: Yageo; Power_W: 100mW; TempCo: 100 ppm/C; Value_Code: 47k5; Value: 47.5k; EIA_Code: E96; SizeX_mm: 1.6; SizeY_mm: 0.8; SizeZ_mm: 1; Value2: 0.1W; SizeArea_mm2: 1.28; AEC Qualified: N; VDC_V: 75V; AEC Category: Q200; SizeAreaWB_mm2: 4.68
R111 = CMP-0022804-5: RES, 14.0 k, 1%, 0.1 W, 0603; Manufacturer: Yageo; Power_W: 100mW; TempCo: 100 ppm/C; Value_Code: 14k0; Value: 14.0k; EIA_Code: E96; Res_ohm: 14k; SizeX_mm: 1.6; SizeY_mm: 0.8; SizeZ_mm: 1; Value2: 0.1W; SizeArea_mm2: 1.28; AEC Qualified: N; VDC_V: 75V; AEC Category: Q200; SizeAreaWB_mm2: 4.68
R112 = CMP-0025886-5: RES, 10 k, 5%, 0.1 W, 0603; Manufacturer: Yageo; Power_W: 100mW; TempCo: 100 ppm/C; Value_Code: 10k0; Value: 10k; EIA_Code: E24; SizeX_mm: 1.6; SizeY_mm: 0.8; SizeZ_mm: 1; Value2: 0.1W; SizeArea_mm2: 1.28; AEC Qualified: N; VDC_V: 75V; AEC Category: Q200; SizeAreaWB_mm2: 4.68
R113 = CMP-0022847-5: RES, 182, 1%, 0.1 W, 0603; Manufacturer: Yageo; Power_W: 100mW; TempCo: 100 ppm/C; Value_Code: 182R; Value: 182; EIA_Code: E96; SizeX_mm: 1.6; SizeY_mm: 0.8; SizeZ_mm: 1; Value2: 0.1W; SizeArea_mm2: 1.28; AEC Qualified: N; VDC_V: 75V; AEC Category: Q200; SizeAreaWB_mm2: 4.68
R116 = CMP-0022588-5: RES, 750, 1%, 0.1 W, AEC-Q200 Grade 0, 0603; Manufacturer: Vishay-Dale; Power_W: 100mW; TempCo: 100 ppm/C; Value_Code: 750R; Value: 750; EIA_Code: E96; SizeX_mm: 1.6; SizeY_mm: 0.8; SizeZ_mm: 1; Value2: 0.1W; SizeArea_mm2: 1.28; AEC Qualified: Y; VDC_V: 75V; AEC Category: Q200; AEC Grade: 0
R117 = CMP-0022822-4: RES, 162 k, 1%, 0.1 W, 0603; Manufacturer: Yageo; Power_W: 100mW; TempCo: 100 ppm/C; Value: 162k; EIA_Code: E96; SizeX_mm: 1.6; SizeY_mm: 0.8; SizeZ_mm: 1; Value2: 0.1W; SizeArea_mm2: 1.28; AEC Qualified: N; VDC_V: 75V; AEC Category: Q200; SizeAreaWB_mm2: 4.68
R118 = CMP-0080488-1: RES, 10.0 k, 1%, 0.1 W, 0603; Manufacturer: TT Electronics/IRC; Power_W: 100mW; TempCo: 100 ppm/C; SizeAreaWB_mm2: 4.68; Value_Code: 10k0; Value: 10.0k; EIA_Code: E96; Res_ohm: 10k; SizeX_mm: 1.6; SizeY_mm: 0.8; SizeZ_mm: 1; Value2: 0.1W; SizeArea_mm2: 1.28; AEC Qualified: N; AEC Category: Q200
R119 = CMP-0022530-4: RES, 604 k, 1%, 0.1 W, AEC-Q200 Grade 0, 0603; Manufacturer: Vishay-Dale; Power_W: 100mW; TempCo: 100 ppm/C; Value: 604k; EIA_Code: E96; SizeX_mm: 1.6; SizeY_mm: 0.8; SizeZ_mm: 1; Value2: 0.1W; SizeArea_mm2: 1.28; AEC Qualified: Y; VDC_V: 75V; AEC Category: Q200; AEC Grade: 0
R120 = CMP-0022812-4: RES, 158 k, 1%, 0.1 W, 0603; Manufacturer: Yageo; Power_W: 100mW; TempCo: 100 ppm/C; Value: 158k; EIA_Code: E96; SizeX_mm: 1.6; SizeY_mm: 0.8; SizeZ_mm: 1; Value2: 0.1W; SizeArea_mm2: 1.28; AEC Qualified: N; VDC_V: 75V; AEC Category: Q200; SizeAreaWB_mm2: 4.68
R121 = CMP-0022808-4: RES, 150 k, 1%, 0.1 W, 0603; Manufacturer: Yageo; Power_W: 100mW; TempCo: 100 ppm/C; Value: 150k; EIA_Code: E96; SizeX_mm: 1.6; SizeY_mm: 0.8; SizeZ_mm: 1; Value2: 0.1W; SizeArea_mm2: 1.28; AEC Qualified: N; VDC_V: 75V; AEC Category: Q200; SizeAreaWB_mm2: 4.68
R123 = CMP-0025697-4: RES, 0, 5%, 0.1 W, AEC-Q200 Grade 0, 0603; Manufacturer: Vishay-Dale; Power_W: 100mW; TempCo: 200 ppm/C; Value_Code: 0000; Value: 0; EIA_Code: E24; SizeX_mm: 1.6; SizeY_mm: 0.8; SizeZ_mm: 1; Value2: 0.1W; SizeArea_mm2: 1.28; AEC Qualified: Y; VDC_V: 75V; AEC Category: Q200
R125 = CMP-0022919-4: RES, 221 k, 1%, 0.1 W, 0603; Manufacturer: Yageo; Power_W: 100mW; TempCo: 100 ppm/C; Value: 221k; EIA_Code: E96; SizeX_mm: 1.6; SizeY_mm: 0.8; SizeZ_mm: 1; Value2: 0.1W; SizeArea_mm2: 1.28; AEC Qualified: N; VDC_V: 75V; AEC Category: Q200; SizeAreaWB_mm2: 4.68
R126 = CMP-0025768-4: RES, 2.0 k, 5%, 0.1 W, AEC-Q200 Grade 0, 0603; Manufacturer: Vishay-Dale; Power_W: 100mW; TempCo: 200 ppm/C; Value_Code: 2k00; Value: 2.0k; EIA_Code: E24; Res_ohm: 2k; SizeX_mm: 1.6; SizeY_mm: 0.8; SizeZ_mm: 1; Value2: 0.1W; SizeArea_mm2: 1.28; AEC Qualified: Y; VDC_V: 75V; AEC Category: Q200; AEC Grade: 0
R127 = CMP-0022879-5: RES, 1.47 k, 1%, 0.1 W, 0603; Manufacturer: Yageo; Power_W: 100mW; TempCo: 100 ppm/C; Value_Code: 1k47; Value: 1.47k; EIA_Code: E96; SizeX_mm: 1.6; SizeY_mm: 0.8; SizeZ_mm: 1; Value2: 0.1W; SizeArea_mm2: 1.28; AEC Qualified: N; VDC_V: 75V; AEC Category: Q200; SizeAreaWB_mm2: 4.68
R128 R129 = CMP-0020631-3: RES, 12, 5%, 0.125 W, AEC-Q200 Grade 0, 0805; Manufacturer: Panasonic; Power_W: 125mW; TempCo: 200 ppm/C; Value_Code: 12R0; Value: 12; EIA_Code: E24; SizeX_mm: 2; SizeY_mm: 1.25; SizeZ_mm: 1.45; Value2: 0.125W; SizeArea_mm2: 2.5; AEC Qualified: Y; VDC_V: 150V; AEC Category: Q200; AEC Grade: 0; SizeAreaWB_mm2: 6.75
R130 R131 = CMP-0025912-5: RES, 330, 5%, 0.1 W, 0603; Manufacturer: Yageo; Power_W: 100mW; TempCo: 100 ppm/C; Value_Code: 330R; Value: 330; EIA_Code: E24; SizeX_mm: 1.6; SizeY_mm: 0.8; SizeZ_mm: 1; Value2: 0.1W; SizeArea_mm2: 1.28; AEC Qualified: N; VDC_V: 75V; AEC Category: Q200; SizeAreaWB_mm2: 4.68
R132 = CMP-0023297-5: RES, 84.5 k, 1%, 0.1 W, 0603; Manufacturer: Yageo; Power_W: 100mW; TempCo: 100 ppm/C; Value_Code: 84k5; Value: 84.5k; EIA_Code: E96; SizeX_mm: 1.6; SizeY_mm: 0.8; SizeZ_mm: 1; Value2: 0.1W; SizeArea_mm2: 1.28; AEC Qualified: N; VDC_V: 75V; AEC Category: Q200; SizeAreaWB_mm2: 4.68
R200 = CMP-0022235-5: RES, 249, 1%, 0.1 W, AEC-Q200 Grade 0, 0603; Manufacturer: Vishay-Dale; Power_W: 100mW; TempCo: 100 ppm/C; Value_Code: 249R; Value: 249; EIA_Code: E96; SizeX_mm: 1.6; SizeY_mm: 0.8; SizeZ_mm: 1; Value2: 0.1W; SizeArea_mm2: 1.28; AEC Qualified: Y; VDC_V: 75V; AEC Category: Q200; AEC Grade: 0
T1 = CMP-0123591-1: LLC TRANSFORMER; Manufacturer: 3L; PartNumber: ATQ27-T-375UH-W6; DCR_ohm: 54m; Ind_H: 375µH; Ns1toNp: 1:0.125:0.125:0.125:0.0625; SizeZ_mm: 27mm; AEC Qualified: No
TP101 TP106 = CMP-0055148-1: Test Point, Multipurpose, Black, TH; Manufacturer: Keystone; CNHeader: FALSE; Green_Lifecycle: Active; Green_REACh: Passed; ContactFinish: Silver; CT: TRUE
U1 = CMP-0040588-2: 36V, microPower, Rail-to-Rail Output, Dual, General Purpose Op Amp in microPackage, DCU0008A (VSSOP-8); Manufacturer: Texas Instruments; Iq per channel(Max)(mA): 0.145; IIB(Max)(pA): 15; CMRR(Min)(dB): 104; Total Supply Voltage(Min)(+5V is 5, +/-5V is 10): 2.7; Eco-Plan: Green (RoHS & no Sb/Br); Total Supply Voltage(Max)(+5V is 5, +/-5V is 10): 36; Number of Channels: 2; Packing: LARGE T&R; Rating: Catalog; GBW(Typ)(MHz): 1.2; Offset Drift(Typ)(uV/C): 0.3; Slew Rate(Typ)(V/us): 0.4; Vio (25C)(Max)(mV): 1.8; AEC Category: Q200; AEC Qualified: N; CompType: IC; SizeAreaWB_mm2: 12.6; SizeArea_mm2: 6.4; SizeX_mm: 3.2; SizeY_mm: 2.0; SizeZ_mm: 0.9
U2 = CMP-0033033-1: Precision Micropower Shunt Voltage Reference, 1% accuracy, 2.5 V, 15 ppm / degC, 15 mA, -40 to 125 degC, 3-pin SOT-23 (DBZ), Green (RoHS & no Sb/Br); Manufacturer: Texas Instruments; Initial Accuracy @ 25/deg C(%): 1; Min Iz for Regulation(uA): 75; Temp Coeff(Typ)(ppm/ degree C): 15; VO(V): 2.5; Rating: Catalog; Temp Coeff(Max)(ppm/ degree C): 150
U101 U103 = CMP-0096535-2: 650-V GaN FET With Integrated Driver and Current Sense Emulation; Manufacturer: Texas Instruments; Number Of Drivers: 1; CompType: IC; Max Supply Voltage: 26V; SizeZ_mm: 1mm; AEC Category: Q200; Min Supply Voltage: 10V; AEC Qualified: No; TJmax_C: +175°C; Standoff Height: 0mm
U102 = CMP-0095300-2: 750kHz Wide VIN/VOUT Range LLC Controller Optimized for Light Load Efficiency; Manufacturer: Texas Instruments; SizeZ_mm: 1.75mm; Number Of Outputs: 2; TaMin_C: -40°C; Standoff Height: 0.1mm; Max Supply Voltage: 18.5V; Switching Topology: Other; TJmax_C: +150°C; TaMax_C: +125°C; AEC Qualified: No; Switching Frequency: 30-750kHz; AEC Category: Q200; CompType: IC
U105 = CMP-0121571-1: Power Supply Controller Flyback, Forward Converters, LLC 8-SOIC; Manufacturer: Monolithic Power Systems; SizeZ_mm: 1.75mm; AEC Qualified: No; Max Power Dissipation: 1.4W; Max Supply Voltage: 35V; Min Supply Voltage: 4.2V; Nominal Supply Current: 4.6-16mA; Number Of Outputs: 2; Standoff Height: 0.1mm; TJmax_C: +125°C

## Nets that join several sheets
PGND: 240W_GaN_PFC_LLC_AC_EMI (BD1.4 BD2.4), 240W_PFC_Stage (51 pins), 240W_LLC_Stage (45 pins)
RTN: 240W_GaN_PFC_LLC_AC_EMI (CY1.2 CY2.2), 240W_LLC_Stage (28 pins)
390V_BUS: 240W_PFC_Stage (7 pins), 240W_LLC_Stage (17 pins)
BD+: 240W_GaN_PFC_LLC_AC_EMI (BD1.1 BD2.1), 240W_PFC_Stage (C25.1 D21.2 D25.2 L22.1)
HV: 240W_GaN_PFC_LLC_AC_EMI (R2.1), 240W_LLC_Stage (U102.1)
TSET: 240W_PFC_Stage (R7.1), 240W_LLC_Stage (R119.1 R121.2 U102.7)
VCCP: 240W_PFC_Stage (Q2.3 R5.1 R6.2), 240W_LLC_Stage (9 pins)

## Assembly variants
001: not fitted C113 CY1 CY2 Q2 R6 R7 R116 R126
